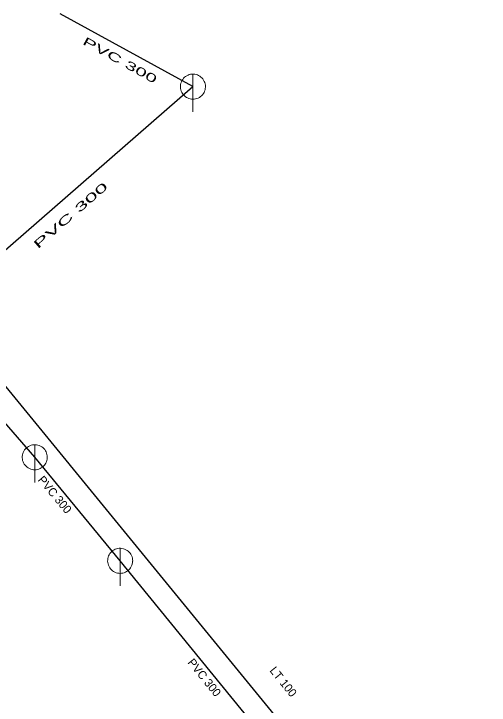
# Model space of a CAD drawing. Extents: x -688296 to -687852, y -973332 to -972816.
# Drawn here: x -688111 to -688073, y -973095.5 to -973040.3 of the extents above; entities that cross this region are included whole.
import ezdxf
from ezdxf.enums import TextEntityAlignment as Align

# ---------------------------------------------------------------- set-up
doc = ezdxf.new("R2010")
doc.units = 0
doc.header["$LTSCALE"] = 0.27
for name, color, linetype, lineweight in [('1', 7, 'Continuous', 25), ('14', 7, 'Continuous', 13), ('17', 7, 'Continuous', 25), ('22', 7, 'Continuous', 13)]:
    doc.layers.add(name, color=color, linetype=linetype, lineweight=lineweight)

msp = doc.modelspace()

# ---------------------------------------------------------------- linework, layer by layer
at = {"layer": '14', "lineweight": 25}
for p, q in [((-688096.66, -973046.13), (-688107.27, -973040.32)), ((-688118.48, -973065.11), (-688096.66, -973046.13)), ((-688085.379, -973104.879), (-688102.469, -973083.96))]:
    msp.add_line(p, q, dxfattribs=at)
msp.add_lwpolyline([(-688102.469, -973083.96), (-688109.289, -973075.699), (-688118.48, -973065.109)], dxfattribs=at)
at = {"layer": '17'}
msp.add_lwpolyline([(-688114.989, -973066.03), (-688114.73, -973066.289), (-688065.039, -973126.929)], dxfattribs=at)
at = {"layer": '22'}
for p, q in [((-688096.66, -973048.13), (-688096.659, -973045.13)), ((-688109.289, -973077.699), (-688109.288, -973074.699)), ((-688102.469, -973085.96), (-688102.468, -973082.96))]:
    msp.add_line(p, q, dxfattribs=at)
for points in [[(-688095.66, -973046.13), (-688095.665, -973046.021), (-688095.683, -973045.913), (-688095.713, -973045.807), (-688095.753, -973045.706), (-688095.805, -973045.609), (-688095.867, -973045.519), (-688095.939, -973045.436), (-688096.019, -973045.362), (-688096.107, -973045.296), (-688096.201, -973045.241), (-688096.301, -973045.196), (-688096.406, -973045.163), (-688096.513, -973045.141), (-688096.622, -973045.131), (-688096.732, -973045.133), (-688096.84, -973045.147), (-688096.947, -973045.172), (-688097.05, -973045.209), (-688097.148, -973045.258), (-688097.24, -973045.316), (-688097.326, -973045.385), (-688097.403, -973045.462), (-688097.472, -973045.548), (-688097.531, -973045.64), (-688097.579, -973045.738), (-688097.616, -973045.841), (-688097.642, -973045.948), (-688097.656, -973046.056), (-688097.659, -973046.166), (-688097.649, -973046.275), (-688097.628, -973046.382), (-688097.594, -973046.486), (-688097.55, -973046.586), (-688097.495, -973046.681), (-688097.429, -973046.769), (-688097.355, -973046.849), (-688097.272, -973046.921), (-688097.182, -973046.983), (-688097.086, -973047.035), (-688096.984, -973047.076), (-688096.879, -973047.106), (-688096.771, -973047.124), (-688096.661, -973047.13), (-688096.552, -973047.124), (-688096.444, -973047.106), (-688096.339, -973047.077), (-688096.237, -973047.036), (-688096.14, -973046.984), (-688096.05, -973046.922), (-688095.967, -973046.851), (-688095.892, -973046.771), (-688095.827, -973046.683), (-688095.771, -973046.589), (-688095.727, -973046.489), (-688095.693, -973046.385), (-688095.671, -973046.277), (-688095.661, -973046.168)], [(-688108.289, -973075.699), (-688108.294, -973075.59), (-688108.312, -973075.482), (-688108.342, -973075.376), (-688108.382, -973075.275), (-688108.434, -973075.178), (-688108.496, -973075.088), (-688108.568, -973075.005), (-688108.648, -973074.931), (-688108.736, -973074.865), (-688108.83, -973074.81), (-688108.93, -973074.765), (-688109.035, -973074.732), (-688109.142, -973074.71), (-688109.251, -973074.7), (-688109.361, -973074.702), (-688109.469, -973074.716), (-688109.576, -973074.741), (-688109.679, -973074.778), (-688109.777, -973074.827), (-688109.869, -973074.885), (-688109.955, -973074.954), (-688110.032, -973075.031), (-688110.101, -973075.117), (-688110.16, -973075.209), (-688110.208, -973075.307), (-688110.245, -973075.41), (-688110.271, -973075.517), (-688110.285, -973075.625), (-688110.288, -973075.735), (-688110.278, -973075.844), (-688110.257, -973075.951), (-688110.223, -973076.055), (-688110.179, -973076.155), (-688110.124, -973076.25), (-688110.058, -973076.338), (-688109.984, -973076.418), (-688109.901, -973076.49), (-688109.811, -973076.552), (-688109.715, -973076.604), (-688109.613, -973076.645), (-688109.508, -973076.675), (-688109.4, -973076.693), (-688109.29, -973076.699), (-688109.181, -973076.693), (-688109.073, -973076.675), (-688108.968, -973076.646), (-688108.866, -973076.605), (-688108.769, -973076.553), (-688108.679, -973076.491), (-688108.596, -973076.42), (-688108.521, -973076.34), (-688108.456, -973076.252), (-688108.4, -973076.158), (-688108.356, -973076.058), (-688108.322, -973075.954), (-688108.3, -973075.846), (-688108.29, -973075.737)], [(-688101.469, -973083.96), (-688101.474, -973083.851), (-688101.492, -973083.743), (-688101.522, -973083.637), (-688101.562, -973083.536), (-688101.614, -973083.439), (-688101.676, -973083.349), (-688101.748, -973083.266), (-688101.828, -973083.192), (-688101.916, -973083.126), (-688102.01, -973083.071), (-688102.11, -973083.026), (-688102.215, -973082.993), (-688102.322, -973082.971), (-688102.431, -973082.961), (-688102.541, -973082.963), (-688102.649, -973082.977), (-688102.756, -973083.002), (-688102.859, -973083.039), (-688102.957, -973083.088), (-688103.049, -973083.146), (-688103.135, -973083.215), (-688103.212, -973083.292), (-688103.281, -973083.378), (-688103.34, -973083.47), (-688103.388, -973083.568), (-688103.425, -973083.671), (-688103.451, -973083.778), (-688103.465, -973083.886), (-688103.468, -973083.996), (-688103.458, -973084.105), (-688103.437, -973084.212), (-688103.403, -973084.316), (-688103.359, -973084.416), (-688103.304, -973084.511), (-688103.238, -973084.599), (-688103.164, -973084.679), (-688103.081, -973084.751), (-688102.991, -973084.813), (-688102.895, -973084.865), (-688102.793, -973084.906), (-688102.688, -973084.936), (-688102.58, -973084.954), (-688102.47, -973084.96), (-688102.361, -973084.954), (-688102.253, -973084.936), (-688102.148, -973084.907), (-688102.046, -973084.866), (-688101.949, -973084.814), (-688101.859, -973084.752), (-688101.776, -973084.681), (-688101.701, -973084.601), (-688101.636, -973084.513), (-688101.58, -973084.419), (-688101.536, -973084.319), (-688101.502, -973084.215), (-688101.48, -973084.107), (-688101.47, -973083.998)]]:
    msp.add_lwpolyline(points, close=True, dxfattribs=at)

# ---------------------------------------------------------------- texts
at = {"layer": '1'}
for rotation, width, p in [(331, 1.85, (-688102.4406, -973044.4174)), (331, 1.85, (-688102.4406, -973044.4174)), (331, 1.85, (-688102.4406, -973044.4174)), (331, 1.85, (-688102.4406, -973044.4174)), (331, 1.85, (-688102.4406, -973044.4174)), (41, 2.1, (-688106.0177, -973056.4826)), (41, 2.1, (-688106.0177, -973056.4826)), (41, 2.1, (-688106.0177, -973056.4826)), (41, 2.1, (-688106.0177, -973056.4826)), (41, 2.1, (-688106.0177, -973056.4826))]:
    msp.add_text('PVC 300 ', height=0.6667, rotation=rotation, dxfattribs=dict(at, width=width)).set_placement(p, align=Align.CENTER)
for s, rotation, p in [('PVC 300 ', 310, (-688107.8595, -973078.9878)), ('PVC 300 ', 310, (-688107.8595, -973078.9878)), ('PVC 300 ', 310, (-688107.8595, -973078.9878)), ('PVC 300 ', 310, (-688107.8595, -973078.9878)), ('PVC 300 ', 310, (-688107.8595, -973078.9878)), ('PVC 300 ', 309, (-688095.9223, -973093.577)), ('PVC 300 ', 309, (-688095.9223, -973093.577)), ('PVC 300 ', 309, (-688095.9223, -973093.577)), ('PVC 300 ', 309, (-688095.9223, -973093.577)), ('PVC 300 ', 309, (-688095.9223, -973093.577)), ('LT 100', 309, (-688089.7004, -973093.8122)), ('LT 100', 309, (-688089.7004, -973093.8122)), ('LT 100', 309, (-688089.7004, -973093.8122)), ('LT 100', 309, (-688089.7004, -973093.8122)), ('LT 100', 309, (-688089.7004, -973093.8122))]:
    msp.add_text(s, height=0.6667, rotation=rotation, dxfattribs=at).set_placement(p, align=Align.CENTER)

doc.saveas('drawing.dxf')
